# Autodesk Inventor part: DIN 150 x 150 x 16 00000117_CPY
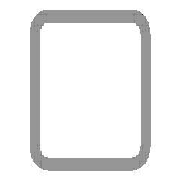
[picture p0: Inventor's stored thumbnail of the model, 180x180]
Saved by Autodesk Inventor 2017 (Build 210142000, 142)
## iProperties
Created: 2017-11
Part Number: DIN 150 x 150 x 16 00000117_CPY
Material: Steel, Mild
Description: Tube
Document SubType Name: Modeling
Standard: DIN
Designer: iusti
Standard Revision: 2006-07
Standards Organization: DIN
Language: en-US
Size Designation: 150 x 150 x 16
Categories: <MemberInstance><Categories><Category DisplayName="Structural Shapes" InternalName="089c4875-fa83-4c05-b084-43b9cc11f5ed" Mnemonic="GRDR"><CategoryParameter Dis
Stock Number: 150 x 150 x 16
Density: 7.85 g/cm^3
Appearance: Semi-Polished
IsCustomPart: 1
_CCFamilyMember: 70
_CCFamilyDisplayName: DIN EN 10210-2 (Square) - Tube — Sizes in parentheses have been withdrawn
_FrameMemberDoc: Frame Member File
_Version: 15.0.0
_GetPNFromCC: 1
Author: iusti
G_L: 2627.460 mm
G_W: 150.000 mm
G_H: 150.000 mm
+945DE835-E5AB-4C66-A99F-F08F7F997FF3+CUTDETAIL1: Cut
+1BDD1E15-33C8-4CBC-9DCD-174E5FBEC9AD+CUTDETAIL2: Cut
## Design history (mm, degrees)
node "Start plane"
node "End plane"
sketch "Sketch"
  geometry: L1 (-75, -51)-(-75, 51); L2 (-51, 75)-(51, 75); L3 (75, 51)-(75, -51); L4 (51, -75)-(-51, -75); L5 (-43, 59)-(43, 59); L6 (59, 43)-(59, -43); L7 (43, -59)-(-43, -59); L8 (-59, -43)-(-59, 43); L9 (0, 111.959)-(0, -111.959) reference; L10 (-111.959, 0)-(111.959, 0) reference; A1 r 24 centre (-51, -51) between (-75, -51) and (-51, -75); A2 r 24 centre (-51, 51) between (-51, 75) and (-75, 51); A3 r 24 centre (51, 51) between (75, 51) and (51, 75); A4 r 24 centre (51, -51) between (51, -75) and (75, -51); A5 r 16 centre (-43, -43) between (-59, -43) and (-43, -59); A6 r 16 centre (-43, 43) between (-43, 59) and (-59, 43); A7 r 16 centre (43, 43) between (59, 43) and (43, 59); A8 r 16 centre (43, -43) between (43, -59) and (59, -43)
  constraints: 16 end point, 16 point on circle, 16 tangent, 8 centre point, 6 equal radius, 4 parallel, 2 perpendicular, 2 other
  dimensions: "d7" = 24 radius of A1 (= G_IR); "d10" = 150 distance between parallel lines of L2 L4 (= G_H); "d11" = 150 distance between parallel lines of L1 L3 (= G_W); "d12" = 16 distance between parallel lines of L3 L6 (= G_T); "d15" = 75 distance between parallel lines of L2 L10 (= 0.5 x d10); "d16" = 75 distance between parallel lines of L9 L3 (= 0.5 x d11); "d19" = 16 radius of A5 (= G_T); "d20" = 16 distance between parallel lines of L4 L7 (= G_T)
extrude "Body" new body sketch "Sketch" stored distance "d3" = 2627.46034 (= G_L); taper "d4" = 0 deg
node "Driven Length"
  sketch "Sketch3"
    geometry: L1 (0, 0)-(10, 0) reference
    constraints: 2 end point, 1 horizontal
  workplane "Work Plane3"
  sketch "Sketch4"
    geometry: L1 (-2, 35.842)-(12, 35.842) reference; L2 (-2, 2663.303)-(12, 2663.303) reference
    dimensions: "d18" = 2627.46034 distance between parallel lines of L1 L2 (derived)
workplane "Work Plane4"
split "Split1"
workplane "Work Plane5"
split "Split2"
body "Solid1"
other parameters: "G_W" = 150 [user parameter; used in 1 equation term], "G_H" = 150 [user parameter; used in 1 equation term], "G_T" = 16 [user parameter; used in 3 equation terms], "G_IR" = 24 [user parameter; used in 1 equation term], "G_L" = 2627.46034 (= d18) [user parameter; used in 1 equation term], "G_OFFSET_START" = -35.84222 [user parameter; used in 1 equation term], "G_OFFSET_END" = 92.90179 [user parameter; used in 1 equation term], "d13" = 35.84222 (= -G_OFFSET_START), "d14" = 2663.30256 (= G_OFFSET_END + B_L), "B_L" = 2570.40077 [user parameter; used in 1 equation term], "d17" = 90 deg
